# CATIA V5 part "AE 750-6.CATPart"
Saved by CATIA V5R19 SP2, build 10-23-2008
Part number: AE 750-6
Bounding box of the stored display mesh (mm): x -24.865 to 24.865, y -24.997 to 24.997, z 0 to 62
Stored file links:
  C:\Users\Bora\Desktop\3D Katı model\AE serisi\AE 750\AE 750-6.CATPart
  C:\Program Files\Dassault Systemes\B19\intel_a\reffiles\standard\MetricThickPitch.txt
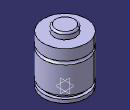
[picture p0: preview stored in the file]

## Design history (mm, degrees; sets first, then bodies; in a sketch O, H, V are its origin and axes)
Body1 (main body)
  Sketch1 on yz-plane, origin (0, 0, 0), H (0, 1, 0), V (0, 0, 1)
    point P1 (25, 38.5)
    point P8 (25, 42.5)
    point P9 (12.5, 60)
    point P11 (12.5, 60)
    point P13 (25, 42.5)
    point P14 (25, 38.5)
    line L1 (25, 38.5) -> (25, 8)
    line L2 (25, 4) -> (25, 0)
    line L3 (21.5, 8) -> (21.5, 4)
    line L4 (25, 55) -> (25, 42.5)
    line L5 (12.5, 60) -> (12.5, 55)
    arc A1 centre (10.5, 60) radius 2 from (12.5, 60) to (10.5, 62) ccw
    arc A2 centre (25, 40.5) radius 2 from (25, 42.5) to (25, 38.5) ccw
    line L6 (10.5, 62) -> (0, 62)
    point P15 (0, 62)
    line L7 (12.5, 55) -> (25, 55)
    line L8 (21.5, 8) -> (25, 8)
    line L9 (21.5, 4) -> (25, 4)
    line L10 (0, 0) -> (25, 0)
    coincidence: P15 V, P1 P14, P8 P13, P9 P11
    tangency: L6 A1
    horizontal: L7 H, L8 H, L9 H, L10 H
  Shaft1: profile Sketch1, axis Sketch1.V, angle 360
  Sketch2 on face of Shaft1 from Sketch1.L10, origin (0, 0, 0), H (1, 0, 0), V (0, -1, 0)
    point P1 (10, 0)
    distance P1 V = 10
  Hole1: placed by Sketch2, at (10, 0, 0) direction (0, 0, 1), diameter 6.647, depth 13, threaded "M8", thread diameter 8, thread depth 13, pitch 1.25
  CircPattern1: of Hole1, instances 2, angular step 180, axis from xy-plane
